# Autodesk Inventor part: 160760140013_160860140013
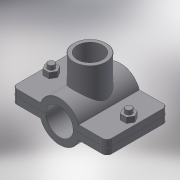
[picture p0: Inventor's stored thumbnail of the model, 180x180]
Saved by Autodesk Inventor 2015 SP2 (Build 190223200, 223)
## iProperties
Created: 2017-05
Part Number: 160760140013_160860140013
Material: Generic
Description: PLASSON SADDLE 140-1.1/4"
Document SubType Name: Modeling
Designer: KIM
Density: 1 g/cm^3
Appearance: Default
Author: KIM
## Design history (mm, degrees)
derived "16076.ipt"
feature "Solid1::16076.ipt"
feature "Solid2::16076.ipt"
tag "TaggingFeature1"
body "Solid1"
other parameters: "d0" = 154, "d1" = 201, "d4" = 136, "d5" = 0, "d6" = 10.05, "d7" = 201, "d8" = 0.1, "d10" = 0, "d11" = 1.4, "d14" = 50.6376, "d20" = 1.4, "d23" = 1.4, "d36" = 15, "d37" = 12, "d38" = 78, "d39" = 0, "d40" = 3, "d41" = 5, "d42" = 0, "d44" = 3, "d45" = 0, "d46" = 1.4, "d51" = 106, "d52" = 38.952, "d53" = 25, "d54" = 0, "d55" = 32, "d57" = 0, "d58" = 151.2, "d60" = 0, "d62" = 15, "d63" = 12, "d66" = 112, "B_" = 32, "G_" = 38.952, "A_" = 106, "L_" = 201, "L_1" = 136, "l_2" = 25
